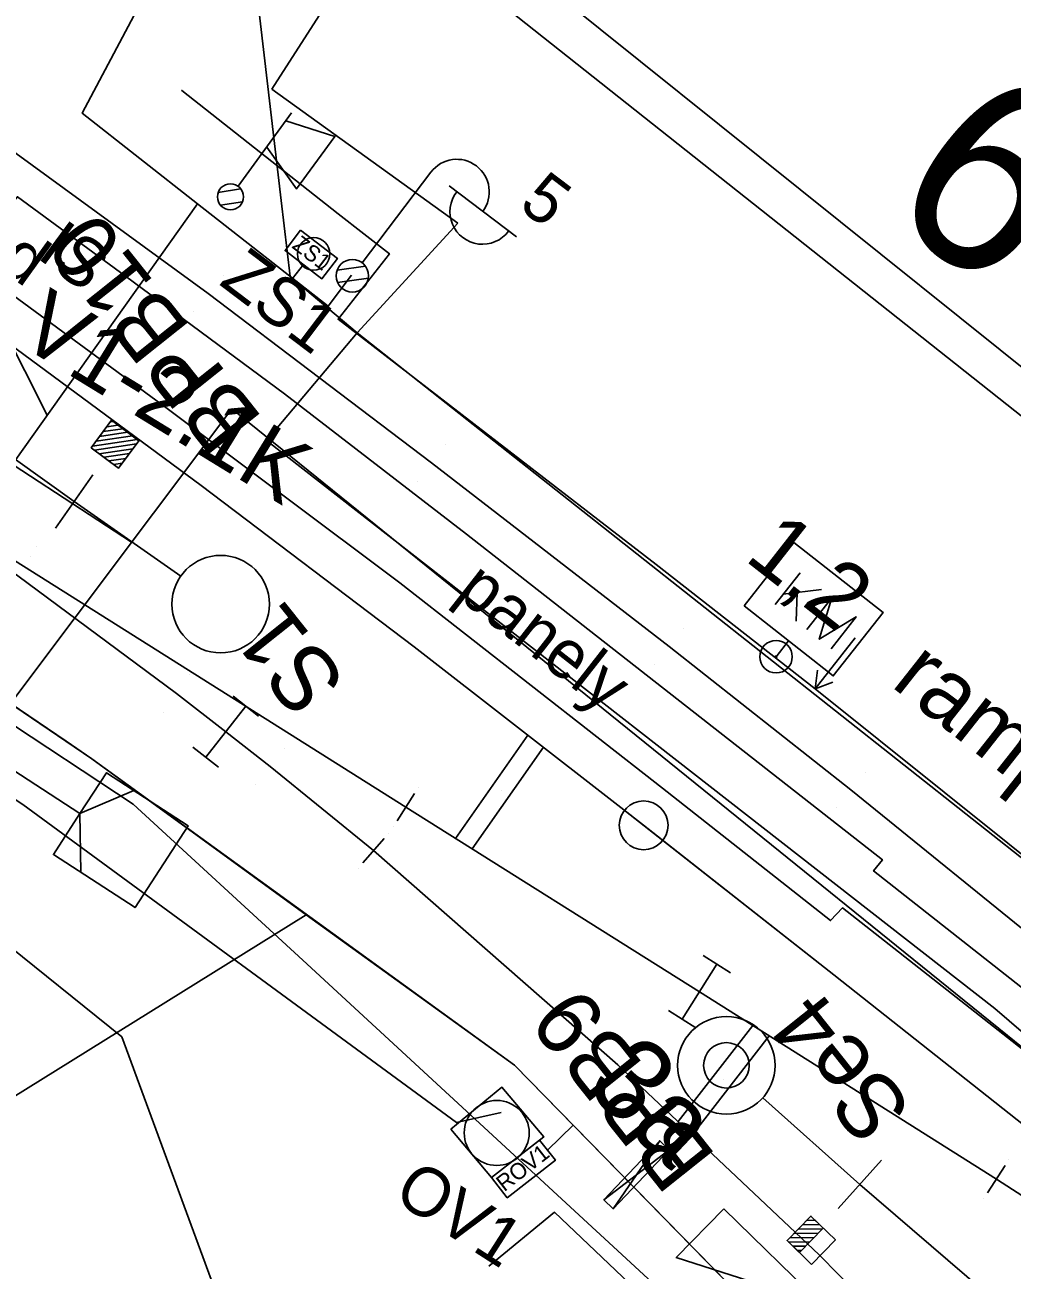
# Model space of a CAD drawing. Extents: x -621145 to -620110, y -1122807 to -1121971.
# Drawn here: x -620312.88 to -620282.51, y -1122695.79 to -1122657.48 of the extents above; entities that cross this region are included whole.
import ezdxf

# ---------------------------------------------------------------- set-up
doc = ezdxf.new("R2010")
doc.units = 0
for name, color, linetype in [('060601_EOV', 7, 'Continuous'), ('060604_ROZVODY_SEE', 7, 'Continuous'), ('POPIS KABELOVÉ TRASY', 7, 'Continuous'), ('PS 06-14-01_trasa_sdělovací_nové', 7, 'Continuous'), ('SEE', 7, 'Continuous'), ('SO 06', 7, 'Continuous'), ('SSZT', 7, 'Continuous'), ('UZEMNĚNÍ', 7, 'Continuous'), ('Vrstva 1', 7, 'Continuous'), ('Vrstva 12', 7, 'Continuous'), ('Vrstva 16', 7, 'Continuous'), ('Vrstva 2', 7, 'Continuous'), ('Vrstva 23', 7, 'Continuous'), ('Vrstva 25', 7, 'Continuous'), ('Vrstva 27', 7, 'Continuous'), ('Vrstva 3', 7, 'Continuous'), ('Vrstva 33', 7, 'Continuous'), ('Vrstva 4', 7, 'Continuous'), ('Vrstva 51', 7, 'Continuous'), ('Vrstva 53', 7, 'Continuous'), ('Vrstva 55', 7, 'Continuous'), ('Vrstva 62', 7, 'Continuous'), ('Vrstva 7', 7, 'Continuous')]:
    doc.layers.add(name, color=color, linetype=linetype)

msp = doc.modelspace()

# ---------------------------------------------------------------- linework, layer by layer
at = {"layer": '060601_EOV'}
msp.add_lwpolyline([(-620235.16, -1122712.242), (-620240.174, -1122718.342), (-620243.025, -1122715.998), (-620248.321, -1122722.765), (-620259.889, -1122713.575), (-620277.713, -1122700.902), (-620282.346, -1122705.302), (-620297.82, -1122689.49), (-620304.222, -1122684.862), (-620310.815, -1122680.061), (-620322.228, -1122672.322), (-620343.182, -1122658.459), (-620368.499, -1122642.897)], dxfattribs=at)
at = {"layer": '060604_ROZVODY_SEE'}
for p, q in [((-620304.307, -1122664.856), (-620304.643, -1122665.284)), ((-620296.802, -1122692.105), (-620296.015, -1122691.335))]:
    msp.add_line(p, q, dxfattribs=at)
for points in [[(-620243.025, -1122715.998), (-620248.321, -1122722.765), (-620259.889, -1122713.575), (-620277.713, -1122700.902), (-620282.346, -1122705.302), (-620297.82, -1122689.49), (-620304.222, -1122684.862), (-620310.815, -1122680.061), (-620316.822, -1122675.988), (-620322.228, -1122672.322), (-620326.634, -1122669.408), (-620343.182, -1122658.459), (-620368.499, -1122642.897), (-620411.557, -1122614.916), (-620424.156, -1122607.087), (-620443.525, -1122595.005), (-620444.244, -1122596.151)], [(-620316.822, -1122675.988), (-620307.569, -1122662.984), (-620311.113, -1122660.198), (-620304.112, -1122646.984), (-620307.038, -1122645.433), (-620340.053, -1122630.257)], [(-620302.826, -1122665.182), (-620303.546, -1122666.133), (-620307.569, -1122662.984)]]:
    msp.add_lwpolyline(points, dxfattribs=at)
for points in [[(-620304.396, -1122663.798), (-620303.263, -1122664.665), (-620303.741, -1122665.29), (-620304.874, -1122664.423)], [(-620298.522, -1122692.948), (-620297.044, -1122691.795), (-620296.56, -1122692.415), (-620298.039, -1122693.568)]]:
    msp.add_lwpolyline(points, close=True, dxfattribs=at)
at = {"layer": 'POPIS KABELOVÉ TRASY'}
for points in [[(-620312.196, -1122669.486), (-620323.97, -1122646.126), (-620330.292, -1122641.833)], [(-620304.222, -1122684.862), (-620317.649, -1122693.211), (-620323.971, -1122688.917)]]:
    msp.add_lwpolyline(points, dxfattribs=at)
at = {"layer": 'PS 06-14-01_trasa_sdělovací_nové'}
msp.add_line((-620296.802, -1122692.105), (-620296.015, -1122691.335), dxfattribs=at)
msp.add_lwpolyline([(-620248.321, -1122722.765), (-620259.889, -1122713.575), (-620277.711, -1122700.887), (-620282.346, -1122705.302), (-620297.82, -1122689.49), (-620310.815, -1122680.061), (-620322.228, -1122672.322), (-620343.182, -1122658.459), (-620368.499, -1122642.897), (-620411.557, -1122614.916), (-620456.111, -1122587.123), (-620544.953, -1122530.859), (-620538.89, -1122521.208), (-620538.89, -1122521.208), (-620538.89, -1122521.208)], dxfattribs=at)
at = {"layer": 'SEE'}
for points in [[(-620244.518, -1122694.296), (-620246.547, -1122692.66), (-620267.469, -1122718.6), (-620268.222, -1122719.534), (-620284.407, -1122704.62), (-620304.333, -1122686.26), (-620309.55, -1122681.453), (-620327.714, -1122669.483), (-620362.834, -1122646.339), (-620390.254, -1122629.02), (-620411.934, -1122614.961), (-620423.125, -1122608.012), (-620468.337, -1122579.91), (-620468.337, -1122579.91), (-620460.94, -1122568.103), (-620517.418, -1122533.032), (-620535.001, -1122522.477), (-620545.407, -1122539.454), (-620611.375, -1122497.696), (-620665.569, -1122462.755)], [(-620340.053, -1122630.257), (-620307.038, -1122645.433), (-620304.995, -1122662.882), (-620304.721, -1122665.223), (-620302.66, -1122666.96), (-620305.446, -1122670.265), (-620283.044, -1122687.742), (-620274.947, -1122694.711), (-620269.357, -1122688.084), (-620267.489, -1122689.555)]]:
    msp.add_lwpolyline(points, dxfattribs=at)
at = {"layer": 'SO 06'}
msp.add_lwpolyline([(-620298.23, -1122690.946), (-620299.598, -1122691.249), (-620312.943, -1122681.47), (-620333.337, -1122667.924), (-620356.709, -1122652.765), (-620357.203, -1122652.946), (-620412.63, -1122616.604), (-620445.655, -1122595.98), (-620446.002, -1122596.548)], dxfattribs=at)
at = {"layer": 'SSZT'}
msp.add_line((-620309.595, -1122673.397), (-620323.304, -1122664.466), dxfattribs=at)
msp.add_lwpolyline([(-620879.238, -1122313.316), (-620842.993, -1122336.61), (-620835.049, -1122343.251), (-620812.66, -1122358.949), (-620764.902, -1122389.752), (-620688.594, -1122438.969), (-620596.981, -1122496.725), (-620576.744, -1122509.484), (-620506.746, -1122556.123), (-620447.293, -1122593.619), (-620363.271, -1122647.563), (-620313.966, -1122679.218), (-620306.51, -1122669.289), (-620273.137, -1122696.274), (-620258.422, -1122709.142), (-620248.072, -1122696.094)], dxfattribs=at)
at = {"layer": 'UZEMNĚNÍ'}
msp.add_line((-620304.307, -1122664.856), (-620304.643, -1122665.284), dxfattribs=at)
msp.add_lwpolyline([(-620302.826, -1122665.182), (-620303.546, -1122666.133), (-620307.569, -1122662.984), (-620311.113, -1122660.198), (-620304.112, -1122646.984), (-620307.038, -1122645.433), (-620340.053, -1122630.257)], dxfattribs=at)
at = {"layer": 'Vrstva 1'}
msp.add_line((-620311.36, -1122672.145), (-620313.165, -1122670.848), dxfattribs=at)
for points in [[(-620348.688, -1122637.935), (-620341.5, -1122642.47), (-620339.854, -1122643.512), (-620333.156, -1122647.798), (-620327.653, -1122651.408), (-620321.139, -1122655.817), (-620314.146, -1122660.717), (-620307.245, -1122665.745), (-620300.366, -1122670.953), (-620293.063, -1122676.601), (-620287.47, -1122681.018), (-620281.24, -1122686.066), (-620276.174, -1122690.251), (-620272.417, -1122693.451), (-620267.757, -1122697.544), (-620266.519, -1122698.689), (-620262.242, -1122702.65), (-620256.103, -1122708.562), (-620249.907, -1122714.621), (-620245.657, -1122718.815), (-620238.557, -1122725.547), (-620230.199, -1122732.623), (-620229.854, -1122732.906)], [(-620347.616, -1122652.305), (-620342.456, -1122655.575), (-620322.526, -1122668.083), (-620312.925, -1122674.13), (-620301.163, -1122681.549), (-620292.126, -1122687.227), (-620282.992, -1122692.997), (-620276.394, -1122697.25), (-620266.758, -1122703.956), (-620255.894, -1122712.191)], [(-620332.789, -1122653.783), (-620326.854, -1122657.769), (-620323.491, -1122660.075), (-620319.328, -1122662.995), (-620318.623, -1122663.494), (-620316.382, -1122665.099), (-620314.967, -1122666.125), (-620314.061, -1122666.783), (-620307.461, -1122671.648), (-620300.906, -1122676.615), (-620294.546, -1122681.556), (-620287.988, -1122686.712), (-620281.909, -1122691.52)], [(-620332.789, -1122653.783), (-620326.854, -1122657.769), (-620323.491, -1122660.075), (-620319.328, -1122662.995), (-620318.623, -1122663.494), (-620316.382, -1122665.099), (-620314.967, -1122666.125), (-620314.061, -1122666.783), (-620307.461, -1122671.648), (-620300.906, -1122676.615), (-620294.546, -1122681.556), (-620293.844, -1122682.108), (-620287.988, -1122686.712), (-620281.909, -1122691.52)], [(-620322.526, -1122668.083), (-620313.097, -1122674.436), (-620308.214, -1122678.053), (-620306.7, -1122679.227), (-620305.337, -1122680.296), (-620302.152, -1122682.886), (-620294.636, -1122689.472), (-620288.443, -1122695.324), (-620284.812, -1122699.019), (-620282.778, -1122701.089), (-620280.313, -1122703.598), (-620275.628, -1122708.447), (-620262.902, -1122721.469), (-620255.487, -1122728.261), (-620248.439, -1122734.187)], [(-620288.271, -1122699.248), (-620297.82, -1122689.49), (-620304.222, -1122684.862), (-620310.815, -1122680.061), (-620311.612, -1122679.521), (-620316.822, -1122675.988)], [(-620277.713, -1122700.902), (-620279.474, -1122699.649), (-620282.292, -1122697.371), (-620287.195, -1122693.156)]]:
    msp.add_lwpolyline(points, dxfattribs=at)
at = {"layer": 'Vrstva 12'}
msp.add_line((-620287.336, -1122676.337), (-620288.569, -1122677.912), dxfattribs=at)
for points in [[(-620280.626, -1122684.271), (-620288.569, -1122677.912), (-620293.461, -1122674.083), (-620303.242, -1122666.538), (-620301.662, -1122664.522), (-620303.242, -1122663.293), (-620308.054, -1122659.497), (-620303.242, -1122663.293), (-620301.662, -1122664.522), (-620303.242, -1122666.538), (-620293.461, -1122674.083), (-620288.569, -1122677.912), (-620280.626, -1122684.271)], [(-620288.497, -1122677.333), (-620288.569, -1122677.912), (-620288.025, -1122677.703)], [(-620299.774, -1122691.456), (-620298.203, -1122690.164), (-620296.914, -1122691.694), (-620298.522, -1122692.948), (-620299.774, -1122691.456)]]:
    msp.add_lwpolyline(points, dxfattribs=at)
at = {"layer": 'Vrstva 16'}
msp.add_lwpolyline([(-620268.767, -1122698.19), (-620269.667, -1122699.332), (-620273.339, -1122696.067), (-620280.591, -1122690.258), (-620287.721, -1122684.651), (-620288.092, -1122685.04), (-620293.259, -1122680.96), (-620301.343, -1122674.65), (-620308.503, -1122669.28), (-620315.629, -1122664.052), (-620319.501, -1122661.293), (-620318.339, -1122659.55), (-620317.166, -1122660.468), (-620313.424, -1122663.148), (-620313.111, -1122662.768), (-620309.78, -1122665.216), (-620304.891, -1122668.836), (-620299.292, -1122673.151), (-620286.498, -1122683.168), (-620286.771, -1122683.508), (-620280.456, -1122688.482), (-620273.255, -1122694.212), (-620268.767, -1122698.19)], dxfattribs=at)
at = {"layer": 'Vrstva 2'}
for p, q in [((-620310.469, -1122669.993), (-620309.867, -1122669.904)), ((-620310.358, -1122669.844), (-620310.016, -1122669.793)), ((-620310.248, -1122669.695), (-620310.165, -1122669.683)), ((-620310.801, -1122670.44), (-620309.42, -1122670.236)), ((-620310.69, -1122670.29), (-620309.569, -1122670.126)), ((-620310.58, -1122670.142), (-620309.718, -1122670.015)), ((-620310.74, -1122670.563), (-620309.443, -1122670.372)), ((-620310.591, -1122670.674), (-620309.554, -1122670.521)), ((-620310.442, -1122670.785), (-620309.664, -1122670.67)), ((-620310.293, -1122670.895), (-620309.775, -1122670.819)), ((-620310.144, -1122671.006), (-620309.886, -1122670.968)), ((-620310.786, -1122671.326), (-620311.934, -1122672.964)), ((-620308.085, -1122674.441), (-620311.36, -1122672.145)), ((-620300.897, -1122681.126), (-620301.429, -1122681.972)), ((-620301.822, -1122682.51), (-620302.482, -1122683.262)), ((-620290.179, -1122690.492), (-620287.195, -1122693.156)), ((-620287.861, -1122693.902), (-620286.529, -1122692.41)), ((-620282.721, -1122692.577), (-620283.263, -1122693.417)), ((-620288.43, -1122694.39), (-620288.953, -1122694.397)), ((-620288.563, -1122694.261), (-620288.824, -1122694.264)), ((-620288.6, -1122694.786), (-620289.342, -1122694.796)), ((-620288.47, -1122694.653), (-620289.212, -1122694.663)), ((-620288.34, -1122694.521), (-620289.083, -1122694.53)), ((-620288.729, -1122694.919), (-620289.383, -1122694.928)), ((-620288.859, -1122695.052), (-620289.25, -1122695.057)), ((-620288.988, -1122695.185), (-620289.117, -1122695.187))]:
    msp.add_line(p, q, dxfattribs=at)
for points in [[(-620322.526, -1122668.083), (-620312.925, -1122674.13), (-620301.163, -1122681.549)], [(-620322.526, -1122668.083), (-620313.097, -1122674.436), (-620308.214, -1122678.053), (-620306.7, -1122679.227), (-620305.337, -1122680.296), (-620302.152, -1122682.886)], [(-620282.992, -1122692.997), (-620276.394, -1122697.25), (-620266.758, -1122703.956), (-620255.894, -1122712.191)]]:
    msp.add_lwpolyline(points, dxfattribs=at)
for points in [[(-620310.212, -1122669.647), (-620309.37, -1122670.274), (-620309.996, -1122671.116), (-620310.839, -1122670.49)], [(-620310.212, -1122669.647), (-620309.37, -1122670.274), (-620309.996, -1122671.116), (-620310.839, -1122670.49)], [(-620291.376, -1122693.905), (-620288.369, -1122696.837), (-620292.842, -1122695.409)], [(-620289.052, -1122695.25), (-620289.428, -1122694.884), (-620288.695, -1122694.132), (-620288.319, -1122694.498)], [(-620289.052, -1122695.25), (-620289.428, -1122694.884), (-620288.695, -1122694.132), (-620288.319, -1122694.498)], [(-620288.676, -1122695.617), (-620289.428, -1122694.884), (-620288.695, -1122694.132), (-620287.943, -1122694.865)]]:
    msp.add_lwpolyline(points, close=True, dxfattribs=at)
for centre, radius in [((-620306.856, -1122675.302), 1.5), ((-620291.298, -1122689.493), 1.5), ((-620291.298, -1122689.493), 0.7)]:
    msp.add_circle(centre, radius, dxfattribs=at)
at = {"layer": 'Vrstva 23'}
msp.add_lwpolyline([(-620292.2, -1122698.187), (-620296.588, -1122694.01), (-620298.602, -1122695.675)], dxfattribs=at)
at = {"layer": 'Vrstva 25'}
for p, q in [((-620302.503, -1122664.801), (-620300.389, -1122662.012)), ((-620299.831, -1122662.435), (-620297.759, -1122664.005)), ((-620304.037, -1122664.496), (-620303.957, -1122664.556)), ((-620303.274, -1122665.028), (-620302.403, -1122664.908)), ((-620303.259, -1122665.404), (-620302.311, -1122665.273))]:
    msp.add_line(p, q, dxfattribs=at)
for centre, radius in [((-620303.997, -1122664.526), 0.5), ((-620302.805, -1122665.2), 0.5), ((-620298.364, -1122691.573), 1)]:
    msp.add_circle(centre, radius, dxfattribs=at)
for centre, start, end in [((-620299.592, -1122662.616), 322.8473, 142.8473), ((-620298.803, -1122663.23), 142.1447, 323.5498)]:
    msp.add_arc(centre, 1, start, end, dxfattribs=at)
at = {"layer": 'Vrstva 3'}
for p, q in [((-620305.689, -1122678.749), (-620306.476, -1122678.132)), ((-620307.317, -1122680.014), (-620306.083, -1122678.44)), ((-620306.924, -1122680.322), (-620307.711, -1122679.705)), ((-620292.66, -1122688.072), (-620291.592, -1122686.382)), ((-620291.169, -1122686.649), (-620292.015, -1122686.115)), ((-620292.237, -1122688.339), (-620293.083, -1122687.805))]:
    msp.add_line(p, q, dxfattribs=at)
at = {"layer": 'Vrstva 33'}
for p, q in [((-620304.673, -1122660.188), (-620306.319, -1122662.447)), ((-620306.93, -1122662.634), (-620306.243, -1122662.526)), ((-620306.86, -1122663.028), (-620306.186, -1122662.922))]:
    msp.add_line(p, q, dxfattribs=at)
msp.add_lwpolyline([(-620304.85, -1122660.43), (-620303.343, -1122660.91), (-620304.521, -1122662.526), (-620305.439, -1122661.239)], dxfattribs=at)
msp.add_circle((-620306.555, -1122662.771), 0.401, dxfattribs=at)
at = {"layer": 'Vrstva 51'}
msp.add_lwpolyline([(-620319.501, -1122661.293), (-620315.629, -1122664.052), (-620308.503, -1122669.28), (-620301.343, -1122674.65), (-620293.259, -1122680.96), (-620288.092, -1122685.04), (-620287.721, -1122684.651), (-620280.591, -1122690.258), (-620273.339, -1122696.067), (-620269.667, -1122699.332)], dxfattribs=at)
at = {"layer": 'Vrstva 53'}
for p, q in [((-620301.83, -1122654.06), (-620305.28, -1122659.46)), ((-620298.73, -1122654.76), (-620265, -1122681.82)), ((-620299.15, -1122656.1), (-620261.22, -1122686.17)), ((-620299.56, -1122663.58), (-620305.28, -1122659.46)), ((-620299.56, -1122663.58), (-620302.66, -1122666.96)), ((-620267.81, -1122694.49), (-620302.66, -1122666.96)), ((-620309.9, -1122688.62), (-620334.71, -1122668.63)), ((-620306.2, -1122698.65), (-620309.9, -1122688.62))]:
    msp.add_line(p, q, dxfattribs=at)
at = {"layer": 'Vrstva 55'}
for p, q in [((-620301.83, -1122654.06), (-620305.28, -1122659.46)), ((-620265, -1122681.82), (-620298.73, -1122654.76)), ((-620261.22, -1122686.17), (-620299.15, -1122656.1)), ((-620305.28, -1122659.46), (-620299.56, -1122663.58)), ((-620299.56, -1122663.58), (-620302.66, -1122666.96)), ((-620302.66, -1122666.96), (-620267.81, -1122694.49)), ((-620309.9, -1122688.62), (-620334.71, -1122668.63)), ((-620306.2, -1122698.65), (-620309.9, -1122688.62))]:
    msp.add_line(p, q, dxfattribs=at)
at = {"layer": 'Vrstva 62'}
for p, q in [((-620306.783, -1122665.199), (-620306.783, -1122665.199)), ((-620307.677, -1122666.314), (-620307.677, -1122666.314)), ((-620299.944, -1122670.391), (-620299.944, -1122670.391)), ((-620300.788, -1122671.515), (-620300.788, -1122671.515)), ((-620312.536, -1122673.534), (-620312.536, -1122673.534)), ((-620312.692, -1122673.835), (-620312.692, -1122673.835)), ((-620292.625, -1122676.047), (-620292.625, -1122676.047)), ((-620293.501, -1122677.156), (-620293.501, -1122677.156)), ((-620307.809, -1122677.461), (-620307.809, -1122677.461)), ((-620308.618, -1122678.645), (-620308.618, -1122678.645)), ((-620306.275, -1122678.641), (-620306.275, -1122678.641)), ((-620307.124, -1122679.813), (-620307.124, -1122679.813)), ((-620304.896, -1122679.744), (-620304.896, -1122679.744)), ((-620287.021, -1122680.479), (-620287.021, -1122680.479)), ((-620305.778, -1122680.848), (-620305.778, -1122680.848)), ((-620300.779, -1122680.954), (-620300.779, -1122680.954)), ((-620287.92, -1122681.558), (-620287.92, -1122681.558)), ((-620301.547, -1122682.144), (-620301.547, -1122682.144)), ((-620301.687, -1122682.347), (-620301.687, -1122682.347)), ((-620302.618, -1122683.425), (-620302.618, -1122683.425)), ((-620291.747, -1122686.622), (-620291.747, -1122686.622)), ((-620292.505, -1122687.832), (-620292.505, -1122687.832)), ((-620294.186, -1122688.929), (-620294.186, -1122688.929)), ((-620295.086, -1122690.014), (-620295.086, -1122690.014)), ((-620282.605, -1122692.402), (-620282.605, -1122692.402)), ((-620283.378, -1122693.592), (-620283.378, -1122693.592)), ((-620287.958, -1122694.78), (-620287.958, -1122694.78))]:
    msp.add_line(p, q, dxfattribs=at)
at = {"layer": 'Vrstva 7'}
for p, q in [((-620289.031, -1122674.335), (-620289.802, -1122675.315)), ((-620288.375, -1122674.851), (-620289.547, -1122674.991)), ((-620289.12, -1122674.94), (-620289.146, -1122675.831)), ((-620289.77, -1122676.92), (-620289.385, -1122676.43)), ((-620289.809, -1122676.889), (-620289.731, -1122676.951)), ((-620299.627, -1122682.514), (-620297.403, -1122679.337)), ((-620299.118, -1122682.834), (-620296.928, -1122679.705)), ((-620311.185, -1122681.748), (-620313.701, -1122680.114)), ((-620298.228, -1122681.039), (-620298.228, -1122681.039)), ((-620292.784, -1122691.222), (-620290.487, -1122688.263)), ((-620292.346, -1122691.636), (-620289.977, -1122688.585)), ((-620291.393, -1122689.919), (-620291.393, -1122689.919)), ((-620295.068, -1122693.629), (-620293.058, -1122692.089))]:
    msp.add_line(p, q, dxfattribs=at)
msp.add_lwpolyline([(-620290.754, -1122675.354), (-620289.22, -1122673.402), (-620286.478, -1122675.557), (-620288.012, -1122677.509)], close=True, dxfattribs=at)
for points in [[(-620288.822, -1122676.086), (-620288.051, -1122675.105), (-620288.443, -1122676.383), (-620287.302, -1122675.694), (-620288.073, -1122676.674)], [(-620311.185, -1122681.748), (-620312.002, -1122683.006), (-620309.487, -1122684.641), (-620307.852, -1122682.125), (-620310.368, -1122680.491), (-620311.185, -1122681.748)], [(-620309.528, -1122681.036), (-620311.185, -1122681.748), (-620311.162, -1122683.552)], [(-620293.349, -1122691.814), (-620294.777, -1122693.904), (-620295.068, -1122693.629), (-620293.349, -1122691.814), (-620293.058, -1122692.089), (-620294.777, -1122693.904)]]:
    msp.add_lwpolyline(points, dxfattribs=at)
for centre, radius in [((-620289.77, -1122676.92), 0.5), ((-620293.844, -1122682.108), 0.75), ((-620293.844, -1122682.108), 0.75)]:
    msp.add_circle(centre, radius, dxfattribs=at)

# ---------------------------------------------------------------- texts
at = {"layer": '060604_ROZVODY_SEE'}
for s, rotation, p in [('ZS1', 322.5799, (-620304.691, -1122664.322)), ('ROV1', 37.9489, (-620298.131, -1122693.398))]:
    msp.add_text(s, height=0.5, rotation=rotation, dxfattribs=at).set_placement(p)
at = {"layer": 'Vrstva 1'}
msp.add_text('3a', height=2.5, rotation=316.6216, dxfattribs=at).set_placement((-620295.691, -1122690.195))
at = {"layer": 'Vrstva 12'}
for s, rotation, p in [('1,2', 321.9495, (-620290.78, -1122673.923)), ('rampa', 321.7315, (-620286.274, -1122677.804))]:
    msp.add_text(s, height=2, rotation=rotation, dxfattribs=at).set_placement(p)
at = {"layer": 'Vrstva 16'}
msp.add_text('panely', height=1.5, rotation=321.941, dxfattribs=at).set_placement((-620299.672, -1122675.04))
at = {"layer": 'Vrstva 25'}
for s, rotation, p in [('5', 322.8473, (-620297.732, -1122663.1)), ('ZS1', 322.8711, (-620306.939, -1122665.446)), ('OV1', 327.3569, (-620301.598, -1122693.603))]:
    msp.add_text(s, height=1.5, rotation=rotation, dxfattribs=at).set_placement(p)
at = {"layer": 'Vrstva 27'}
msp.add_text('V1-2.1K', height=2, rotation=328.4879, dxfattribs=at).set_placement((-620313.166, -1122667.242))
at = {"layer": 'Vrstva 3'}
for s, height, rotation, p in [('IS', 1.5, 323.6053, (-620312.548, -1122664.624)), ('BPB10', 2, 128.542, (-620305.526, -1122669.616)), ('S1', 2, 128.542, (-620302.932, -1122677.683)), ('BPB9', 2, 128.542, (-620291.576, -1122692.306)), ('Se4', 2, 128.542, (-620285.524, -1122690.835))]:
    msp.add_text(s, height=height, rotation=rotation, dxfattribs=at).set_placement(p)
at = {"layer": 'Vrstva 4'}
msp.add_text('Přejezd', height=1.5, rotation=324.2373, dxfattribs=at).set_placement((-620318.371, -1122661.606))
at = {"layer": 'Vrstva 7'}
msp.add_text('63,4', height=6, rotation=321.8255, dxfattribs=at).set_placement((-620286.609, -1122663.084))

doc.saveas('drawing.dxf')
